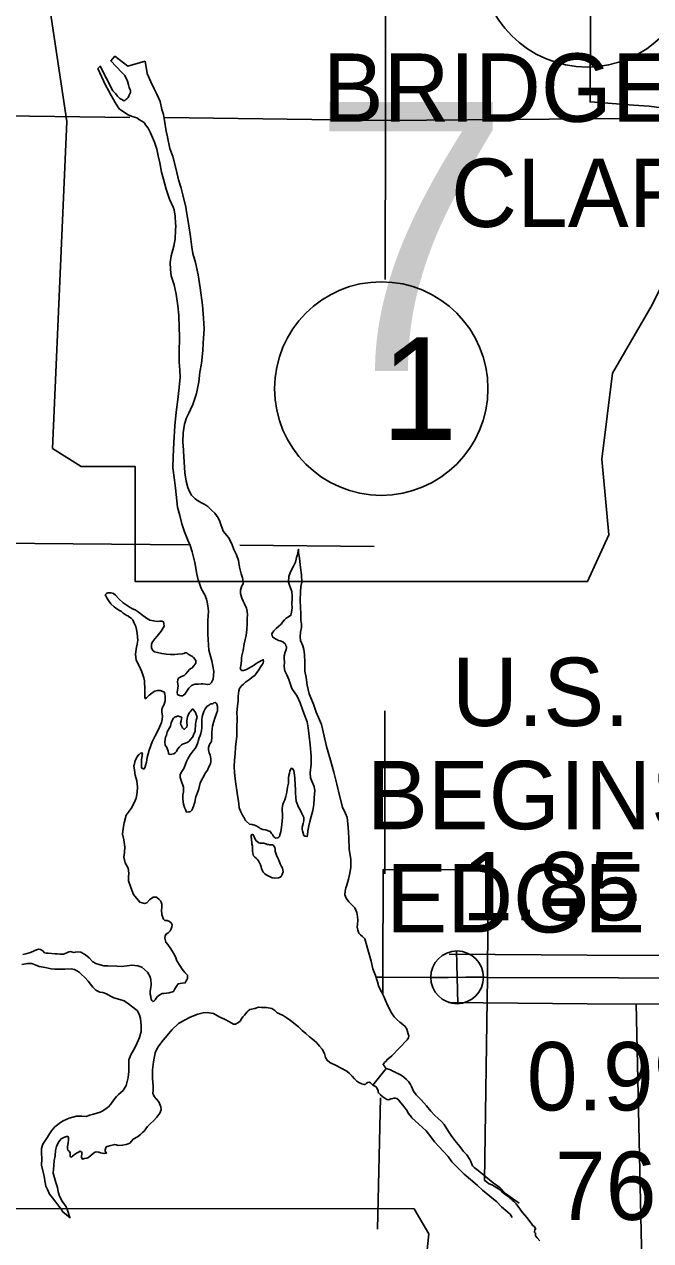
# Model space of a CAD drawing. Extents: x 369523 to 838377, y 495025 to 936819.
# Drawn here: x 570168 to 577918, y 795383 to 810419 of the extents above; entities that cross this region are included whole.
import ezdxf

# ---------------------------------------------------------------- set-up
doc = ezdxf.new("R2010")
doc.units = 0
for name, color, linetype in [('21', 7, 'Continuous'), ('22', 7, 'Continuous'), ('DSN_BRDG_Annotation', 7, 'Continuous'), ('DSN_DRFT_Common-Annotations', 7, 'Continuous'), ('DSN_DRFT_Common-Line', 7, 'Continuous'), ('DSN_DRFT_Junk-No-Plot', 7, 'Continuous'), ('Level 1', 7, 'Continuous'), ('Level 10', 7, 'Continuous'), ('Level 2', 7, 'Continuous'), ('Level 22', 7, 'Continuous')]:
    doc.layers.add(name, color=color, linetype=linetype)

msp = doc.modelspace()

# ---------------------------------------------------------------- linework, layer by layer
at = {"layer": '22'}
for points in [[(570296, 811882), (570696, 809217), (570518, 805176), (570873, 804954), (571539, 804954), (571539, 803533), (577135, 803533), (577401, 804110), (577313, 805043), (577446, 806108), (577934, 806952), (578245, 807574), (578689, 808240), (578956, 808951), (579178, 809528), (579577, 810016), (579666, 810327), (579489, 810549), (578112, 810549), (578423, 811171), (578467, 811571), (578283, 811878)], [(567003, 795779), (567402, 793115), (567225, 789073), (567580, 788851), (568246, 788851), (568246, 787430), (573842, 787430), (574108, 788007), (574019, 788940), (574153, 790006), (574641, 790850), (574952, 791471), (575396, 792138), (575662, 792848), (575884, 793425), (576284, 793914), (576373, 794225), (576195, 794447), (574819, 794447), (575130, 795069), (575174, 795468), (574990, 795775)]]:
    msp.add_lwpolyline(points, close=True, dxfattribs=at)
msp.add_lwpolyline([(575139, 791752), (577882, 791740), (577739, 798309)], dxfattribs=at)
at = {"layer": 'DSN_DRFT_Common-Annotations'}
for p, q in [((575530, 798313), (575514, 798964)), ((575197, 798631), (575847, 798646))]:
    msp.add_line(p, q, dxfattribs=at)
msp.add_circle((575522, 798638), 326, dxfattribs=at)
at = {"layer": 'DSN_DRFT_Common-Line'}
for centre in [(577131, 811211), (574584, 805916)]:
    msp.add_circle(centre, 1320, dxfattribs=at)
at = {"layer": 'Level 1'}
for points in [[(581664, 798865), (581202, 798886), (580968, 798885), (580733, 798889), (580581, 798896), (580237, 798910), (579831, 798917), (579535, 798912), (579189, 798917), (578346, 798908), (577133, 798910), (575423, 798926)], [(582203, 798239), (581188, 798286), (580963, 798285), (580715, 798289), (580555, 798297), (580220, 798310), (579831, 798317), (579536, 798312), (579187, 798317), (578349, 798308), (577130, 798310), (575417, 798326)]]:
    msp.add_lwpolyline(points, dxfattribs=at)
at = {"layer": 'Level 10'}
for points in [[(571076, 809871), (571105, 809902), (571262, 809596), (571299, 809561), (571319, 809533), (571348, 809504), (571366, 809492), (571402, 809475), (571412, 809477), (571426, 809489), (571436, 809497), (571451, 809514), (571463, 809534), (571475, 809558), (571480, 809576), (571480, 809602), (571467, 809638), (571457, 809670), (571444, 809716), (571431, 809747), (571421, 809767), (571413, 809785), (571388, 809811), (571374, 809825), (571238, 809968), (571288, 810025), (571448, 809900), (571663, 809962)], [(572128, 802119), (572138, 802125), (572154, 802137), (572171, 802165), (572185, 802186), (572204, 802214), (572220, 802230), (572238, 802245), (572277, 802262), (572321, 802264), (572357, 802265), (572377, 802265), (572409, 802262), (572437, 802256), (572463, 802261), (572483, 802281), (572506, 802322), (572512, 802418), (572486, 802550), (572449, 802681), (572438, 802881), (572439, 803051), (572447, 803164), (572437, 803232), (572429, 803277), (572422, 803313), (572401, 803367), (572362, 803438), (572341, 803494), (572320, 803552), (572303, 803622), (572276, 803767), (572257, 803849), (572246, 803897), (572220, 803977), (572191, 804042), (572151, 804146), (572118, 804243), (572092, 804349), (572064, 804452), (572038, 804686), (572022, 804816), (572007, 804938), (572009, 805074), (572016, 805248), (572030, 805455), (572045, 805623), (572066, 805782), (572085, 805931), (572095, 806059), (572091, 806143), (572084, 806241), (572082, 806345), (572086, 806567), (572084, 806665), (572079, 806824), (572069, 806938), (572046, 807083), (572020, 807199), (571986, 807310), (571975, 807388), (571974, 807474), (571986, 807559), (572018, 807676), (572036, 807766), (572040, 807874), (572041, 807926), (572039, 807958), (572035, 808046), (572022, 808124), (572009, 808160), (571963, 808257), (571925, 808381), (571889, 808504), (571867, 808592), (571845, 808708), (571826, 808795), (571806, 808877), (571777, 808961), (571752, 809018), (571731, 809076), (571700, 809134), (571669, 809177), (571651, 809205), (571594, 809240), (571562, 809265), (571502, 809278), (571451, 809301), (571407, 809329), (571377, 809348), (571344, 809371), (571326, 809399), (571293, 809451), (571272, 809490), (571243, 809540), (571210, 809603), (571171, 809667), (571076, 809871)], [(571663, 809962), (571690, 809812), (571735, 809709), (571773, 809623), (571806, 809554), (571848, 809463), (571869, 809367), (571891, 809303), (571902, 809231), (571924, 809100), (571941, 809028), (571940, 809024), (571970, 808886), (572004, 808785), (572047, 808625), (572077, 808498), (572109, 808392), (572130, 808312), (572165, 808157), (572169, 808131), (572205, 807929), (572223, 807797), (572240, 807665), (572255, 807588), (572287, 807474), (572320, 807321), (572345, 807161), (572372, 806949), (572385, 806787), (572392, 806655), (572381, 806477), (572377, 806386), (572359, 806226), (572341, 806121), (572326, 806001), (572298, 805854), (572253, 805719), (572226, 805659), (572205, 805614), (572176, 805554), (572151, 805475), (572133, 805371), (572131, 805259), (572137, 805155), (572138, 805137), (572146, 805009), (572154, 804873), (572172, 804771), (572191, 804695), (572210, 804645), (572237, 804598), (572280, 804552), (572322, 804523), (572369, 804500), (572403, 804483), (572437, 804459), (572490, 804408), (572525, 804375), (572566, 804319), (572588, 804274), (572628, 804154), (572696, 804075), (572735, 803998), (572762, 803926), (572792, 803861), (572819, 803791), (572832, 803709), (572852, 803626), (572869, 803578), (572873, 803560), (572874, 803504), (572860, 803477), (572843, 803425), (572844, 803381), (572859, 803327), (572876, 803288), (572892, 803254), (572915, 803202), (572924, 803162), (572929, 803120), (572927, 803076), (572925, 803012), (572922, 802936), (572911, 802862), (572900, 802813), (572889, 802761), (572875, 802679), (572860, 802612), (572856, 802586), (572853, 802558), (572852, 802512), (572848, 802492), (572841, 802470), (572839, 802460), (572843, 802452), (572845, 802438), (572855, 802432), (572867, 802430), (572879, 802429), (572915, 802443), (572953, 802462)], [(573598, 800671), (573619, 800632), (573627, 800614), (573627, 800580), (573622, 800556), (573618, 800540), (573605, 800493), (573604, 800467), (573610, 800447), (573625, 800391), (573637, 800384), (573649, 800382), (573667, 800378), (573673, 800394), (573676, 800450), (573687, 800511), (573700, 800565), (573718, 800627), (573739, 800700), (573748, 800774), (573754, 800852), (573759, 800907), (573761, 800943), (573756, 800999), (573727, 801064), (573710, 801106), (573705, 801168), (573715, 801274), (573719, 801374), (573704, 801512), (573693, 801618), (573681, 801724), (573667, 801798), (573638, 801872), (573611, 801949), (573581, 802033), (573542, 802114), (573513, 802154), (573476, 802207), (573461, 802259), (573442, 802319), (573417, 802376), (573392, 802426), (573386, 802448), (573383, 802486), (573385, 802536), (573384, 802580), (573383, 802614), (573394, 802658), (573408, 802690), (573411, 802710), (573411, 802722), (573405, 802742), (573399, 802756), (573368, 802786), (573332, 802797), (573312, 802803), (573282, 802818), (573278, 802818), (573239, 802846), (573233, 802863), (573231, 802879), (573238, 802900), (573242, 802906), (573254, 802922), (573283, 802952), (573315, 802981), (573344, 803002), (573364, 803028), (573387, 803056), (573407, 803077), (573438, 803093), (573466, 803114), (573475, 803152), (573480, 803206), (573479, 803256), (573482, 803318), (573482, 803351), (573477, 803407), (573453, 803474), (573437, 803524), (573439, 803592), (573456, 803640), (573478, 803683), (573497, 803721), (573522, 803772), (573533, 803806), (573537, 803826), (573542, 803854), (573552, 803884), (573561, 803929), (573562, 803891), (573564, 803865), (573571, 803823), (573576, 803777), (573585, 803705), (573599, 803613), (573600, 803521), (573591, 803469), (573583, 803400), (573582, 803302)], [(571713, 802125), (571679, 802095), (571664, 802082), (571661, 802102), (571660, 802190), (571656, 802302), (571647, 802340), (571620, 802416), (571588, 802487), (571551, 802557), (571542, 802633), (571554, 802721), (571563, 802757), (571571, 802805), (571570, 802843), (571563, 802893), (571554, 802937), (571546, 802973), (571529, 803017), (571512, 803057), (571488, 803080), (571455, 803100), (571455, 803102), (571427, 803115), (571393, 803141), (571369, 803160), (571346, 803174), (571300, 803203), (571278, 803217), (571239, 803254), (571219, 803282), (571202, 803309), (571190, 803331), (571175, 803355), (571169, 803365), (571185, 803381), (571203, 803390), (571239, 803392), (571271, 803381), (571295, 803361), (571336, 803318), (571393, 803267), (571441, 803234), (571477, 803208), (571506, 803195), (571540, 803179), (571576, 803158), (571617, 803125), (571678, 803078), (571722, 803054), (571768, 803047), (571812, 803038), (571844, 803041), (571870, 803041), (571888, 803033), (571896, 803012), (571897, 802980), (571862, 802919), (571811, 802854), (571782, 802821), (571757, 802791), (571743, 802761), (571740, 802732), (571742, 802712), (571750, 802691), (571761, 802675), (571779, 802663), (571817, 802654), (571869, 802641), (571929, 802632), (571977, 802627), (572029, 802627), (572069, 802632), (572123, 802637), (572141, 802642), (572160, 802650), (572180, 802648), (572195, 802634), (572225, 802615), (572247, 802605), (572263, 802592), (572290, 802554), (572289, 802520), (572267, 802490), (572240, 802461), (572230, 802455), (572212, 802443), (572187, 802416), (572167, 802390), (572144, 802369), (572114, 802355), (572076, 802336), (572067, 802320), (572065, 802288), (572070, 802240), (572061, 802159), (572064, 802134), (572090, 802120), (572106, 802116), (572118, 802116), (572128, 802119)], [(573582, 803302), (573586, 803208), (573589, 803136), (573591, 803054), (573598, 803002), (573596, 802962), (573585, 802906), (573581, 802846), (573587, 802802), (573614, 802738), (573625, 802690), (573634, 802630), (573640, 802532), (573640, 802424), (573656, 802344), (573669, 802251), (573691, 802141), (573745, 802016), (573779, 801918), (573806, 801849), (573844, 801763), (573857, 801711), (573905, 801492), (573956, 801321), (573996, 801175), (574033, 801024), (574070, 800870), (574104, 800743), (574143, 800663), (574162, 800613), (574176, 800496), (574181, 800361), (574189, 800221), (574207, 800096), (574209, 799995), (574194, 799927), (574180, 799851), (574153, 799766), (574144, 799744), (574137, 799702), (574135, 799656), (574150, 799618), (574183, 799572), (574224, 799529), (574256, 799496), (574271, 799470), (574283, 799440), (574290, 799388), (574293, 799340), (574292, 799300), (574288, 799258), (574295, 799222), (574308, 799186), (574326, 799165), (574352, 799141), (574379, 799113), (574428, 798952), (574460, 798837), (574481, 798741), (574513, 798659), (574536, 798582), (574555, 798522), (574586, 798460), (574619, 798393), (574636, 798353), (574667, 798284), (574709, 798198), (574742, 798151), (574776, 798115), (574813, 798082), (574851, 798053), (574878, 798029), (574902, 797996), (574917, 797940), (574924, 797916), (574920, 797892), (574906, 797865), (574716, 797668), (574669, 797629), (574653, 797617), (574648, 797606), (574624, 797584), (574607, 797560), (574645, 797510), (574479, 797307), (574449, 797335), (574435, 797340), (574415, 797338), (574397, 797326), (574385, 797315), (574371, 797313), (574343, 797321), (574305, 797338), (574281, 797356), (574254, 797383), (574226, 797417), (574191, 797450), (574157, 797479), (574080, 797518), (574036, 797543), (573949, 797586)], [(572953, 802462), (572982, 802480), (573010, 802499), (573037, 802518), (573065, 802536), (573081, 802542), (573101, 802553), (573113, 802557), (573124, 802563), (573127, 802541), (573123, 802525), (573113, 802511), (573094, 802480), (573071, 802438), (573036, 802395), (573020, 802371), (572987, 802348), (572953, 802320), (572904, 802285), (572878, 802264), (572853, 802240), (572829, 802207), (572822, 802181), (572813, 802115), (572814, 802055), (572805, 801995), (572799, 801908), (572800, 801850), (572801, 801804), (572799, 801760), (572796, 801618), (572779, 801484), (572776, 801401), (572769, 801323), (572765, 801243), (572770, 801171), (572778, 801093), (572785, 801029), (572796, 800949), (572807, 800885), (572817, 800815), (572821, 800783), (572828, 800734), (572845, 800682), (572872, 800634), (572884, 800618), (572903, 800577), (572913, 800569), (572955, 800532), (572988, 800526), (573030, 800517), (573074, 800490), (573088, 800478), (573118, 800466), (573154, 800463), (573209, 800442), (573225, 800418), (573237, 800402), (573252, 800381), (573268, 800365), (573276, 800357), (573304, 800364), (573316, 800372), (573326, 800378), (573331, 800398), (573343, 800436), (573346, 800465), (573349, 800495), (573353, 800529), (573358, 800571), (573361, 800609), (573363, 800653), (573360, 800701), (573359, 800729), (573366, 800773), (573380, 800808), (573391, 800832), (573405, 800874), (573412, 800908), (573415, 800932), (573426, 800987), (573436, 801039), (573436, 801103), (573440, 801133), (573447, 801163), (573455, 801185), (573466, 801216), (573470, 801220), (573480, 801222), (573501, 801194), (573505, 801168), (573512, 801136), (573514, 801102), (573518, 801012), (573523, 800960), (573524, 800920), (573527, 800860), (573533, 800814), (573561, 800743), (573577, 800717), (573598, 800671)], [(571910, 799147), (571920, 799169), (571949, 799190), (571971, 799212), (571984, 799239), (571994, 799263), (571996, 799285), (571985, 799311), (571965, 799330), (571937, 799340), (571907, 799339), (571890, 799359), (571880, 799377), (571871, 799415), (571864, 799469), (571868, 799501), (571869, 799541), (571863, 799569), (571854, 799585), (571838, 799600), (571804, 799628), (571762, 799627), (571718, 799598), (571683, 799561), (571657, 799551), (571597, 799568), (571518, 799661), (571484, 799750), (571459, 799832), (571456, 799880), (571463, 799926), (571452, 799986), (571417, 800055), (571399, 800125), (571406, 800181), (571411, 800251), (571398, 800339), (571382, 800407), (571391, 800477), (571402, 800546), (571428, 800642), (571488, 800727), (571529, 800796), (571552, 800853), (571565, 800923), (571567, 800995), (571560, 801069), (571541, 801139), (571530, 801201), (571525, 801251), (571530, 801277), (571540, 801317), (571563, 801362), (571576, 801384), (571588, 801392), (571606, 801408), (571626, 801415), (571630, 801407), (571628, 801393), (571626, 801379), (571623, 801353), (571619, 801331), (571618, 801298), (571616, 801282), (571617, 801258), (571617, 801234), (571623, 801224), (571627, 801221), (571635, 801221), (571643, 801215), (571651, 801217), (571657, 801223), (571661, 801227), (571668, 801255), (571678, 801298), (571689, 801356), (571713, 801448), (571749, 801549), (571786, 801624), (571817, 801676), (571842, 801729), (571867, 801788), (571874, 801824), (571877, 801866), (571870, 801922), (571870, 801948), (571883, 801986), (571895, 802004), (571912, 802057), (571911, 802091), (571911, 802115), (571906, 802137), (571904, 802149), (571902, 802163), (571896, 802169), (571882, 802172), (571847, 802184), (571817, 802183), (571784, 802175), (571764, 802162), (571713, 802125)], [(571937, 801673), (571975, 801743), (571984, 801786), (571996, 801814), (572013, 801842), (572025, 801854), (572037, 801857), (572047, 801859), (572059, 801867), (572077, 801867), (572101, 801860), (572109, 801858), (572117, 801850), (572113, 801832), (572108, 801808), (572102, 801780), (572103, 801764), (572119, 801730), (572125, 801722), (572140, 801706), (572148, 801706), (572161, 801717), (572175, 801731), (572177, 801731), (572183, 801755), (572180, 801787), (572178, 801811), (572189, 801859), (572194, 801880), (572204, 801900), (572216, 801914), (572223, 801926), (572235, 801942), (572245, 801951), (572255, 801955), (572283, 801921), (572290, 801901), (572305, 801855), (572295, 801819), (572284, 801767), (572285, 801743), (572281, 801711), (572282, 801679), (572264, 801649), (572251, 801612)], [(572343, 801043), (572327, 800969), (572319, 800943), (572292, 800868), (572287, 800848), (572278, 800802), (572270, 800778), (572261, 800751), (572259, 800745), (572249, 800723), (572240, 800705), (572230, 800691), (572220, 800685), (572198, 800682), (572176, 800680), (572170, 800688), (572163, 800714), (572151, 800737), (572136, 800779), (572129, 800839), (572130, 800893), (572136, 800933), (572137, 800961), (572137, 800989), (572130, 801013), (572118, 801047), (572098, 801107), (572098, 801145), (572115, 801181), (572140, 801218), (572158, 801262), (572175, 801308), (572190, 801341), (572219, 801387), (572243, 801422), (572258, 801436), (572280, 801467), (572299, 801495), (572316, 801539), (572320, 801557), (572333, 801600), (572345, 801628), (572352, 801652), (572359, 801690), (572365, 801724), (572364, 801754), (572364, 801778), (572363, 801808), (572365, 801831), (572367, 801853), (572372, 801873), (572376, 801887), (572380, 801901), (572391, 801925), (572397, 801941), (572407, 801959), (572412, 801970), (572432, 801990), (572454, 802002), (572467, 802013), (572481, 802017), (572493, 802021), (572503, 802025), (572513, 802031), (572529, 802034), (572539, 802032), (572547, 802024), (572547, 802022), (572553, 802008), (572556, 802000), (572558, 801986), (572560, 801956), (572559, 801936), (572557, 801932), (572545, 801898), (572536, 801874), (572528, 801854)], [(572528, 801854), (572507, 801787), (572498, 801743), (572493, 801711), (572488, 801659), (572488, 801629), (572489, 801601), (572482, 801556), (572476, 801540), (572460, 801518), (572455, 801504), (572447, 801478), (572446, 801452), (572454, 801414), (572467, 801384), (572473, 801362), (572476, 801338), (572474, 801306), (572471, 801278), (572457, 801249), (572436, 801199), (572434, 801197), (572409, 801165), (572343, 801043)], [(572251, 801612), (572226, 801578), (572208, 801559), (572184, 801543), (572161, 801531), (572127, 801520), (572111, 801512), (572086, 801489), (572064, 801457), (572049, 801430), (572033, 801412), (572019, 801402), (571995, 801397), (571972, 801393), (571953, 801399), (571951, 801415), (571947, 801433), (571932, 801478), (571910, 801506), (571907, 801548), (571914, 801608), (571927, 801632), (571937, 801673)], [(572990, 800258), (572984, 800288), (572981, 800308), (572977, 800328), (572977, 800356), (572976, 800366), (572974, 800394), (572978, 800400), (572988, 800404), (572996, 800402), (573004, 800390), (573010, 800380), (573012, 800372), (573018, 800359), (573025, 800347), (573033, 800335), (573037, 800327), (573045, 800321), (573069, 800301), (573086, 800296), (573109, 800296), (573119, 800298), (573133, 800296), (573145, 800293), (573156, 800289), (573172, 800281), (573188, 800279), (573200, 800278), (573212, 800278), (573224, 800276), (573238, 800274), (573246, 800272), (573252, 800267), (573266, 800243), (573273, 800223), (573273, 800197), (573290, 800149), (573307, 800103)], [(573307, 800103), (573317, 800088), (573334, 800040), (573348, 800010), (573363, 799986), (573369, 799942), (573358, 799908), (573345, 799886), (573325, 799873), (573313, 799869), (573259, 799864), (573235, 799866), (573203, 799883), (573160, 799907), (573138, 799920), (573124, 799936), (573114, 799956), (573103, 799982), (573099, 800004), (573090, 800027), (573082, 800047), (573066, 800077), (573055, 800093), (573039, 800109), (573021, 800124), (573002, 800142), (572994, 800174), (572991, 800198), (572990, 800258)], [(570149, 798921), (570187, 798930), (570243, 798943), (570290, 798964), (570318, 798976), (570342, 798985), (570368, 798981), (570396, 798964), (570418, 798942), (570440, 798936), (570464, 798935), (570550, 798928), (570574, 798929), (570612, 798925), (570650, 798926), (570652, 798926), (570696, 798939), (570710, 798949), (570724, 798955), (570738, 798956), (570752, 798952), (570780, 798946), (570800, 798951), (570829, 798955), (570866, 798950), (570924, 798915), (570969, 798880), (571015, 798829), (571054, 798809), (571106, 798792), (571152, 798779), (571202, 798782), (571314, 798774), (571370, 798771), (571440, 798782), (571499, 798787), (571571, 798779), (571620, 798765), (571693, 798701), (571720, 798651), (571732, 798613), (571739, 798547), (571734, 798511), (571727, 798467), (571725, 798431), (571732, 798401), (571734, 798387), (571739, 798367), (571745, 798351), (571757, 798339), (571769, 798342), (571777, 798350), (571785, 798358), (571800, 798382), (571816, 798400), (571845, 798423), (571875, 798440), (571893, 798440), (571959, 798447), (572012, 798462), (572026, 798488), (572040, 798509), (572071, 798557), (572120, 798564), (572160, 798571), (572170, 798595), (572178, 798609), (572185, 798625), (572187, 798639), (572185, 798663), (572152, 798699), (572121, 798738), (572092, 798786), (572057, 798843), (572039, 798891), (572014, 798937), (571981, 798990), (571942, 799042), (571920, 799073), (571909, 799107), (571907, 799123), (571910, 799147)], [(570956, 798589), (570915, 798637), (570872, 798676), (570846, 798701), (570788, 798734), (570747, 798742), (570670, 798740), (570632, 798738), (570544, 798740), (570500, 798741), (570424, 798760), (570352, 798773), (570303, 798794), (570261, 798807), (570211, 798810), (570137, 798797)], [(570765, 796427), (570755, 796419), (570744, 796415), (570738, 796419), (570735, 796429), (570737, 796463), (570726, 796484), (570706, 796502), (570704, 796518), (570703, 796546), (570710, 796594), (570716, 796624), (570715, 796660), (570707, 796670), (570691, 796672), (570665, 796664), (570624, 796641), (570592, 796602), (570567, 796548), (570554, 796499), (570548, 796433), (570539, 796373), (570532, 796311), (570529, 796267), (570527, 796219), (570540, 796161), (570560, 796103), (570577, 796039), (570588, 795985), (570603, 795932), (570638, 795872), (570685, 795801), (570712, 795735), (570725, 795689), (570735, 795666), (570644, 795738), (570625, 795770), (570597, 795809), (570556, 795859), (570515, 795912), (570478, 795959), (570459, 796007), (570435, 796057), (570424, 796101), (570423, 796123), (570417, 796154), (570408, 796196), (570399, 796244), (570382, 796318), (570385, 796394), (570381, 796468), (570382, 796524), (570397, 796575), (570454, 796664), (570481, 796702), (570506, 796741), (570547, 796788), (570616, 796843), (570648, 796866), (570721, 796897), (570814, 796923), (570880, 796922), (570936, 796919), (570976, 796934), (571023, 796946), (571065, 796957), (571107, 796972), (571133, 796984), (571166, 797003), (571210, 797038), (571237, 797072), (571274, 797125), (571309, 797166), (571335, 797188), (571392, 797241), (571430, 797302), (571451, 797399), (571463, 797473), (571460, 797541), (571463, 797617), (571487, 797680), (571534, 797765), (571565, 797829), (571593, 797896), (571614, 797970), (571613, 798044), (571607, 798128), (571590, 798182), (571565, 798226), (571495, 798281), (571458, 798312), (571402, 798347), (571349, 798364), (571277, 798383), (571235, 798404), (571186, 798433), (571140, 798450), (571102, 798456), (571054, 798479), (571017, 798518), (570956, 798589)], [(573949, 797586), (573913, 797613), (573896, 797649), (573883, 797695), (573852, 797748), (573822, 797788), (573783, 797831), (573734, 797874), (573698, 797904), (573653, 797945), (573607, 797982), (573560, 798025), (573463, 798106), (573408, 798141), (573370, 798168), (573325, 798185), (573297, 798199), (573269, 798226), (573232, 798254), (573164, 798267), (573102, 798267), (573066, 798269), (573021, 798254), (572959, 798239), (572939, 798224), (572924, 798210), (572892, 798172), (572873, 798149), (572857, 798123), (572838, 798096), (572822, 798082), (572810, 798074), (572780, 798059), (572756, 798061), (572708, 798086), (572644, 798119), (572587, 798144), (572509, 798191), (572430, 798203), (572381, 798200), (572313, 798181), (572220, 798147), (572149, 798108), (572077, 798067), (571993, 797989), (571936, 797920), (571887, 797863), (571821, 797774), (571789, 797703), (571765, 797593), (571756, 797494), (571756, 797388), (571762, 797294), (571761, 797234), (571760, 797206), (571774, 797164), (571831, 797097), (571856, 797039), (571861, 797002), (571846, 796959), (571807, 796908), (571766, 796862), (571730, 796831), (571693, 796794), (571650, 796735), (571631, 796719), (571607, 796695), (571570, 796668), (571514, 796637), (571473, 796586), (571451, 796580), (571428, 796571), (571384, 796562), (571328, 796561), (571306, 796567), (571286, 796573), (571222, 796557), (571181, 796541), (571169, 796504), (571169, 796490), (571184, 796463), (571154, 796460), (571134, 796464), (571112, 796467), (571088, 796475), (571058, 796480), (571046, 796478), (571022, 796464), (570961, 796411), (570941, 796404), (570912, 796398), (570886, 796391), (570877, 796409), (570877, 796421), (570879, 796461), (570878, 796477), (570860, 796487), (570838, 796476), (570815, 796464), (570785, 796445), (570765, 796427)], [(574700, 797495), (574645, 797510)], [(574728, 797476), (574700, 797495)], [(576291, 795845), (576236, 795885), (576123, 795967), (576054, 796034), (575967, 796098), (575876, 796171), (575782, 796249), (575734, 796288), (575711, 796308), (575705, 796328), (575692, 796360), (575680, 796388), (575641, 796443), (575602, 796484), (575555, 796545), (575494, 796620), (575451, 796682), (575418, 796733), (575363, 796818), (575330, 796856), (575289, 796891), (575241, 796934), (575198, 796982), (575145, 797051), (575078, 797122), (575017, 797187), (574984, 797230), (574959, 797288), (574944, 797315), (574920, 797351), (574897, 797377), (574863, 797404), (574843, 797422), (574822, 797431), (574788, 797449), (574770, 797458), (574758, 797466), (574728, 797476)], [(574520, 797284), (574479, 797307)], [(576205, 795670), (576181, 795710), (576072, 795802), (576013, 795863), (575928, 795931), (575837, 796008), (575774, 796063), (575715, 796118), (575611, 796206), (575506, 796306), (575459, 796358), (575410, 796423), (575353, 796484), (575298, 796545), (575243, 796606), (575198, 796665), (575138, 796740), (575047, 796823), (575002, 796866), (574962, 796903), (574958, 796909), (574923, 796955), (574898, 796998), (574876, 797026), (574849, 797057), (574825, 797087), (574808, 797109), (574800, 797121), (574778, 797140), (574762, 797144), (574742, 797146), (574726, 797141), (574702, 797135), (574686, 797129), (574670, 797124), (574654, 797126), (574628, 797144), (574606, 797157), (574573, 797185), (574565, 797192), (574549, 797210), (574547, 797222), (574544, 797236), (574536, 797254), (574526, 797276), (574520, 797284)]]:
    msp.add_lwpolyline(points, dxfattribs=at)
at = {"layer": 'Level 2'}
for points in [[(577174, 810576), (577168, 809459), (577547, 809434), (577706, 809421), (577900, 809406), (578107, 809380), (578273, 809359), (578436, 809341), (578794, 809312), (579003, 809294), (579164, 809279), (579469, 809253), (579563, 809246), (579605, 809244), (579643, 809247), (579667, 809252), (579683, 809259), (579695, 809271), (579704, 809285)], [(575899, 798636), (575906, 799965), (574606, 799971), (574602, 798640), (575899, 798636)], [(575899, 798636), (575860, 796128)], [(579142, 798627), (575899, 798636)], [(575860, 796128), (575876, 796117), (575912, 796089), (575959, 796067), (576066, 796001), (576074, 795988), (576142, 795935), (576181, 795905), (576199, 795897), (576207, 795880), (576219, 795871), (576253, 795840), (576332, 795730), (576387, 795671), (576440, 795598), (576455, 795574), (576478, 795555), (576495, 795526), (576485, 795521), (576480, 795486), (576493, 795476), (576491, 795442), (576511, 795419), (576546, 795379)]]:
    msp.add_lwpolyline(points, dxfattribs=at)
at = {"layer": 'Level 22'}
for points in [[(574634, 807263), (574637, 809231), (574641, 812350)], [(569299, 809297), (571474, 809268)], [(571903, 809269), (574637, 809231), (579702, 809270), (580284, 809261)], [(572198, 803986), (569342, 804011)], [(574495, 803963), (572833, 803980)], [(574630, 799919), (574629, 801931)], [(574605, 798641), (574525, 798638)], [(574605, 798641), (574603, 798435)], [(574539, 795525), (574576, 797147)]]:
    msp.add_lwpolyline(points, dxfattribs=at)

# ---------------------------------------------------------------- texts
at = {"layer": '21'}
for s, p in [('BRIDGES SHOWN ON', (573860, 809214)), ('CLARK CO. LOG', (575448, 807914)), ('U.S. 67, SECTION 7', (575459, 801745)), ('BEGINS AT THE TRAIL', (574407, 800469)), ('EDGE OF THE BRIDGE', (574646, 799193))]:
    msp.add_text(s, height=844.8, dxfattribs=at).set_placement(p)
at = {"layer": '22'}
msp.add_text('7', height=3326, dxfattribs=at).set_placement((573714, 806133))
at = {"layer": 'DSN_BRDG_Annotation'}
msp.add_text('1.85', height=844.8, dxfattribs=at).set_placement((575585, 799342))
at = {"layer": 'DSN_DRFT_Common-Line'}
msp.add_text('1', height=1267, dxfattribs=at).set_placement((574584, 805282))
at = {"layer": 'DSN_DRFT_Junk-No-Plot'}
for s, p in [('0.99', (576384, 796993)), ('76.81', (576733, 795639))]:
    msp.add_text(s, height=844.8, dxfattribs=at).set_placement(p)

doc.saveas('drawing.dxf')
